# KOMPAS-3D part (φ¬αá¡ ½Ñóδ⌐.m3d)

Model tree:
1. Эскиз:1
2. Операция выдавливания:1
     Расстояние 1 = 1; Расстояние 2 = 3.7
3. Эскиз:2
4. Операция выдавливания:2
     Расстояние 1 = 0.5; Расстояние 2 = 3.7
5. Эскиз:3
6. Операция выдавливания:3
     Расстояние 1 = 4.8; Расстояние 2 = 3.7
7. Скругление:1
     Радиус = 1
8. Эскиз:4
9. Операция выдавливания:4
     Расстояние 1 = 0.3
10. Массив по сетке:1  (with: Операция выдавливания:4)  (labels: Экземпляр ( 1, 1 ); Экземпляр ( 2, 1 ); Экземпляр ( 3, 1 ); Экземпляр ( 4, 1 ))
     N 1 = 33; Шаг 1 = 8; Угол раствора = 90; N 2 = 1; Номер 1 = 1; Номер 2 = 1
11. Эскиз:6
12. Вырезать элемент выдавливания:1
     Расстояние 1 = 10
13. Фаска:2
     Угол = 63.4349; Длина 1 = 2.5; Длина 2 = 5
14. Эскиз:7
15. Операция выдавливания:6
     Расстояние 1 = 0.3
16. Массив по сетке:3  (with: Операция выдавливания:6)  (labels: Экземпляр ( 1, 1 ); Экземпляр ( 2, 1 ); Экземпляр ( 3, 1 ); Экземпляр ( 4, 1 ))
     N 1 = 6; Шаг 1 = 8; Угол раствора = 90; N 2 = 1; Номер 1 = 1; Номер 2 = 1
17. Эскиз:8
18. Операция выдавливания:7
     Расстояние 1 = 0.3
19. Скругление:2
     Радиус = 0.3
20. Скругление:3
     Радиус = 0.3

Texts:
  Сплав АЛ8  ГОСТ 1583-93
  stalker61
